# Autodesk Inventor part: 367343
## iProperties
Created: 2006-08
Part Number: 367343
Material: 8.8 vz
Description: Zylinderschraube
Vendor: Autodesk Inc.
Document SubType Name: Modeling
Standard: DIN 912
Designer: I.Baliuc
Standards Organization: DIN
Language: de-DE
Size Designation: M10 x 20
Categories: <MemberInstance Version="R10.0.0"><Categories><Category DisplayName="Schrauben" InternalName="e4da775c-781d-43d5-af7c-5136215cf5a6" Mnemonic="FSTN"><Category Di
Density: 7.85 g/cm^3
Mass: 25.3035 g
Surface Area: 16.4669 cm^2
Volume: 3.22338 cm^3
Abmessung: M10 x 20
Author: T.Messerschmitt
Comments: DIN 912 - M10 x 20
Revision Number: 367343
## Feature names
1. Körper [Revolution]
2. Loch [Extrusion]
3. Rundung1 [Fillet]
4. Fase1 [Chamfer]
